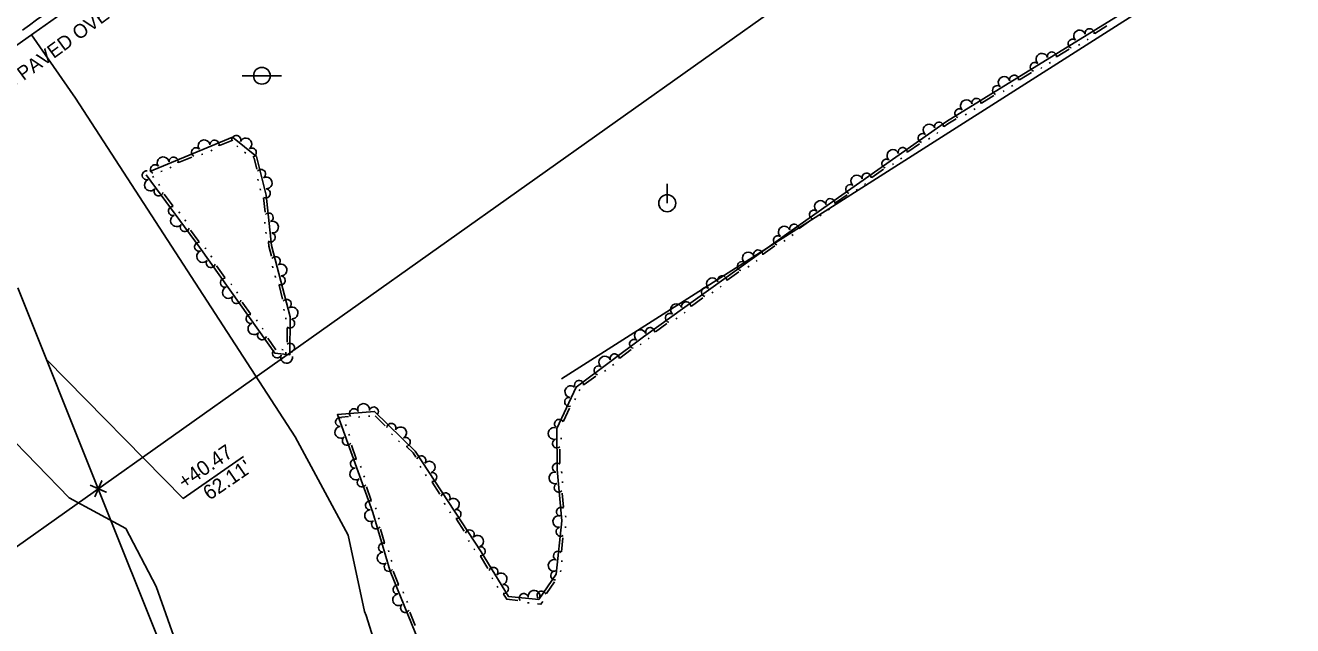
# Model space of a CAD drawing. Extents: x 1577032 to 1581865, y 611492 to 615011.
# Drawn here: x 1579793.8 to 1580157.3, y 613153.4 to 613325.8 of the extents above; entities that cross this region are included whole.
import ezdxf

# ---------------------------------------------------------------- set-up
doc = ezdxf.new("R2010")
doc.units = 0
for name, color, linetype in [('Exist Hydro Jurisdictional Stream or Body of Water', 7, 'Continuous'), ('Exist Other Culture Fence Line', 7, 'Continuous'), ('Exist Property Corner CELL', 7, 'Continuous'), ('Exist Property Line', 7, 'Continuous'), ('Exist Property Tie Line', 7, 'Continuous'), ('Exist Property Tie Line Leader', 7, 'Continuous'), ('Exist Property Tie Line Text', 7, 'Continuous'), ('Exist Right of Way Line', 7, 'Continuous'), ('Exist Roads EOT', 7, 'Continuous'), ('Exist Structure Major Deck Tunnel Box Culvert', 7, 'Continuous'), ('Exist Utilities Power Pole CELL', 7, 'Continuous'), ('Exist Utilities Telephone Pole CELL', 7, 'Continuous'), ('Old_Level_11', 7, 'Continuous'), ('Scratch_Level_3', 7, 'Continuous')]:
    doc.layers.add(name, color=color, linetype=linetype)

msp = doc.modelspace()

# ---------------------------------------------------------------- linework, layer by layer
at = {"layer": 'Exist Hydro Jurisdictional Stream or Body of Water'}
for points in [[(1579795.54, 613323.09), (1579808.15, 613304.86)], [(1579891.06, 613157.43), (1579886.36, 613179.34), (1579871.2, 613207.59), (1579808.15, 613304.86)], [(1579831.32, 613164.67), (1579822.56, 613181.34), (1579806.35, 613190.1), (1579787.81, 613209.26), (1579780.85, 613233.72), (1579753.99, 613271.61), (1579747.82, 613283.64), (1579744.18, 613286.7)], [(1579849.47, 613068.48), (1579851.27, 613081.33), (1579854.07, 613093.1), (1579856.83, 613105.74), (1579850.56, 613123.2), (1579837.45, 613147.36), (1579831.32, 613164.67)], [(1579881.95, 612966.49), (1579883.81, 612978.96), (1579885.26, 612993.89), (1579884.04, 613006.43), (1579886.63, 613016.25), (1579894.51, 613030.46), (1579900.22, 613050.87), (1579903.43, 613069.8), (1579906.17, 613093.25), (1579900.39, 613127.87), (1579891.53, 613156.32), (1579891.06, 613157.43)]]:
    msp.add_lwpolyline(points, dxfattribs=at)
at = {"layer": 'Exist Other Culture Fence Line'}
msp.add_line((1579947.54, 613224.25), (1580319.1, 613460.95), dxfattribs=at)
at = {"layer": 'Exist Property Corner CELL'}
msp.add_line((1579814.68, 613192.73), (1579814.68, 613192.73), dxfattribs=at)
msp.add_lwpolyline([(1579812.38, 613193.72), (1579816.97, 613191.75), (1579814.68, 613192.73), (1579815.66, 613195.03), (1579813.69, 613190.43)], dxfattribs=at)
at = {"layer": 'Exist Property Line'}
msp.add_line((1579859.46, 613080.55), (1579814.68, 613192.73), dxfattribs=at)
at = {"layer": 'Exist Property Tie Line'}
msp.add_line((1579791.65, 613250.42), (1579814.68, 613192.73), dxfattribs=at)
at = {"layer": 'Exist Property Tie Line Leader'}
msp.add_lwpolyline([(1579799.92, 613229.7), (1579839.05, 613189.94), (1579856.37, 613202.02)], dxfattribs=at)
at = {"layer": 'Exist Right of Way Line'}
msp.add_line((1578304.92, 612120.6), (1580458.22, 613649.74), dxfattribs=at)
at = {"layer": 'Exist Roads EOT'}
msp.add_lwpolyline([(1579792.91, 613324.43), (1579794.95, 613325.88), (1579796.98, 613327.33), (1579799.02, 613328.78), (1579801.06, 613330.23), (1579803.09, 613331.68), (1579805.13, 613333.13), (1579807.17, 613334.58), (1579809.21, 613336.02), (1579811.26, 613337.46), (1579813.3, 613338.89), (1579815.35, 613340.33), (1579817.39, 613341.77), (1579819.44, 613343.21), (1579821.48, 613344.64), (1579823.53, 613346.08), (1579825.57, 613347.52), (1579826.09, 613347.88)], dxfattribs=at)
at = {"layer": 'Exist Structure Major Deck Tunnel Box Culvert'}
msp.add_lwpolyline([(1579827.3, 613348.19), (1579814.88, 613365.36), (1579813.5, 613367.27), (1579799.63, 613357.47), (1579792.53, 613352.42), (1579770.02, 613336.52), (1579752.16, 613323.84), (1579739.02, 613314.56), (1579723.58, 613303.6), (1579719.7, 613300.83), (1579716.41, 613298.3), (1579718.14, 613295.84), (1579729.17, 613280.12), (1579731.04, 613277.46), (1579735.17, 613280.34), (1579753.85, 613293.54), (1579777.85, 613310.57), (1579796.19, 613323.54), (1579810.87, 613333.95), (1579825.71, 613344.51), (1579828.51, 613346.49)], close=True, dxfattribs=at)
at = {"layer": 'Exist Utilities Power Pole CELL'}
for q in [(1579977.88, 613280.32), (1579977.88, 613274.7)]:
    msp.add_line((1579977.88, 613274.7), q, dxfattribs=at)
msp.add_circle((1579977.88, 613274.7), 2.45, dxfattribs=at)
at = {"layer": 'Exist Utilities Telephone Pole CELL'}
for p, q in [((1579855.95, 613311.31), (1579867.28, 613311.31)), ((1579861.62, 613311.31), (1579861.62, 613311.31))]:
    msp.add_line(p, q, dxfattribs=at)
msp.add_circle((1579861.62, 613311.31), 2.41, dxfattribs=at)
at = {"layer": 'Old_Level_11'}
for points in [[(1579898.24, 612986.26), (1579907.01, 613012.55), (1579914.07, 613035.38), (1579922.37, 613060.98), (1579924.18, 613085.02), (1579920.71, 613110.77), (1579911.67, 613136.42), (1579898.39, 613169.04), (1579893.39, 613185.86), (1579883.29, 613213.99), (1579893.92, 613214.92), (1579905.6, 613203.51), (1579924.51, 613174.57), (1579932.36, 613161.75), (1579941.05, 613160.87), (1579945.99, 613168.16), (1579947.64, 613183.49), (1579946.28, 613198.23), (1579946.25, 613210.04), (1579951.72, 613221.88), (1579971.1, 613236.34), (1580013.43, 613266.8), (1580057.96, 613298.21), (1580109, 613329.66)], [(1580100.52, 613323.47), (1580104.01, 613325.63)], [(1580098.29, 613321.62), (1580098.64, 613321.84)], [(1580089.7, 613316.8), (1580093.19, 613318.96)], [(1580095.85, 613320.11), (1580096.2, 613320.33)], [(1580085.03, 613313.44), (1580085.38, 613313.66)], [(1580087.47, 613314.95), (1580087.82, 613315.16)], [(1580078.88, 613310.13), (1580082.37, 613312.29)], [(1580074.2, 613306.77), (1580074.55, 613306.99)], [(1580076.65, 613308.28), (1580077, 613308.49)], [(1580068.05, 613303.46), (1580071.54, 613305.62)], [(1580057.32, 613296.75), (1580058.41, 613297.53), (1580060.72, 613298.95)], [(1580063.38, 613300.1), (1580063.73, 613300.32)], [(1580065.82, 613301.61), (1580066.17, 613301.82)], [(1579829.46, 613283.82), (1579853.23, 613293.7), (1579860.11, 613288.12), (1579862.87, 613276.99), (1579864.41, 613262.57), (1579869.72, 613242.08), (1579869.67, 613231.18), (1579865.28, 613231.66), (1579855.5, 613245.54), (1579843.72, 613262.07), (1579828.46, 613282.9)], [(1579849.47, 613291.25), (1579853.25, 613292.83)], [(1580046.93, 613289.42), (1580050.28, 613291.79)], [(1580052.87, 613293.11), (1580053.2, 613293.35)], [(1580055.21, 613294.76), (1580055.54, 613295)], [(1579837.73, 613286.37), (1579841.51, 613287.95)], [(1579844.32, 613288.67), (1579844.7, 613288.83)], [(1579846.97, 613289.77), (1579847.35, 613289.93)], [(1579854.44, 613291.14), (1579854.76, 613290.88)], [(1579856.67, 613289.33), (1579856.99, 613289.07)], [(1579859.16, 613287.84), (1579859.38, 613287.66), (1579860.16, 613284.49)], [(1579835.24, 613284.89), (1579835.61, 613285.05)], [(1580036.54, 613282.1), (1580039.89, 613284.46)], [(1580042.47, 613285.78), (1580042.81, 613286.02)], [(1580044.82, 613287.43), (1580045.15, 613287.67)], [(1579830.55, 613282.13), (1579830.31, 613282.46)], [(1579832.58, 613283.79), (1579832.96, 613283.95)], [(1579860.46, 613281.61), (1579860.56, 613281.21)], [(1579832.25, 613279.82), (1579832.01, 613280.15)], [(1579836.04, 613273.95), (1579833.61, 613277.26)], [(1579861.15, 613278.82), (1579861.24, 613278.42)], [(1580026.15, 613274.77), (1580029.5, 613277.13)], [(1580032.09, 613278.45), (1580032.42, 613278.69)], [(1580034.43, 613280.11), (1580034.77, 613280.35)], [(1579862.12, 613276.23), (1579862.56, 613272.15)], [(1579838.06, 613271.88), (1579837.82, 613272.21)], [(1579839.76, 613269.56), (1579839.52, 613269.89)], [(1580015.76, 613267.44), (1580019.11, 613269.81)], [(1580021.7, 613271.13), (1580022.03, 613271.36)], [(1580024.04, 613272.78), (1580024.38, 613273.02)], [(1579843.55, 613263.69), (1579841.12, 613267)], [(1579862.46, 613269.25), (1579862.5, 613268.84)], [(1579862.76, 613266.4), (1579862.81, 613265.99)], [(1579863.48, 613263.59), (1579863.6, 613262.42), (1579864.37, 613259.47)], [(1580005.44, 613260.04), (1580008.77, 613262.43)], [(1580011.33, 613263.78), (1580011.67, 613264.02)], [(1580013.66, 613265.45), (1580014, 613265.69)], [(1579845.57, 613261.59), (1579845.33, 613261.93)], [(1579847.23, 613259.25), (1579847, 613259.59)], [(1579850.95, 613253.34), (1579848.57, 613256.68)], [(1579864.69, 613256.59), (1579864.79, 613256.19)], [(1580001.02, 613256.35), (1580001.35, 613256.59)], [(1580003.35, 613258.03), (1580003.68, 613258.27)], [(1579852.95, 613251.24), (1579852.71, 613251.57)], [(1579865.41, 613253.81), (1579865.51, 613253.41)], [(1579995.12, 613252.61), (1579998.45, 613255.01)], [(1579854.62, 613248.9), (1579854.38, 613249.24)], [(1579866.53, 613251.13), (1579867.55, 613247.16)], [(1579990.7, 613248.93), (1579991.03, 613249.17)], [(1579993.03, 613250.6), (1579993.36, 613250.84)], [(1579858.31, 613242.97), (1579856.17, 613246.02), (1579855.95, 613246.33)], [(1579867.88, 613244.28), (1579867.98, 613243.88)], [(1579984.8, 613245.19), (1579988.13, 613247.58)], [(1579860.3, 613240.86), (1579860.07, 613241.2)], [(1579868.49, 613241.8), (1579868.49, 613241.39)], [(1579980.38, 613241.5), (1579980.71, 613241.74)], [(1579982.71, 613243.18), (1579983.04, 613243.42)], [(1579861.95, 613238.52), (1579861.72, 613238.85)], [(1579868.88, 613238.93), (1579868.87, 613234.83)], [(1579974.48, 613237.76), (1579977.81, 613240.16)], [(1579865.63, 613232.58), (1579863.27, 613235.93)], [(1579970.1, 613234.06), (1579970.43, 613234.3)], [(1579972.39, 613235.75), (1579972.72, 613235.99)], [(1579867.72, 613232.63), (1579867.31, 613232.67)], [(1579868.44, 613231.96), (1579868.44, 613231.55)], [(1579964.27, 613230.22), (1579967.55, 613232.67)], [(1579959.91, 613226.45), (1579960.24, 613226.7)], [(1579962.21, 613228.17), (1579962.54, 613228.42)], [(1579954.08, 613222.61), (1579957.36, 613225.07)], [(1579952.61, 613220.87), (1579952.78, 613221.24)], [(1579948.11, 613212.11), (1579949.83, 613215.83)], [(1579951.41, 613218.26), (1579951.58, 613218.63)], [(1579884.42, 613213.26), (1579886.44, 613213.44)], [(1579889.33, 613213.28), (1579889.74, 613213.32)], [(1579892.19, 613213.53), (1579892.6, 613213.57)], [(1579894.08, 613213.62), (1579897.02, 613210.75)], [(1579885.76, 613210.75), (1579885.62, 613211.13)], [(1579886.73, 613208.05), (1579886.59, 613208.43)], [(1579898.78, 613208.45), (1579899.08, 613208.16)], [(1579947.48, 613209.77), (1579947.45, 613209.7)], [(1579888.7, 613201.35), (1579887.31, 613205.21)], [(1579900.84, 613206.44), (1579901.13, 613206.16)], [(1579903.18, 613204.73), (1579904.96, 613202.99), (1579905.74, 613201.79)], [(1579947.49, 613206.96), (1579947.48, 613207.37)], [(1579947.1, 613199.99), (1579947.09, 613204.09)], [(1579890.06, 613198.78), (1579889.92, 613199.17)], [(1579906.97, 613199.17), (1579907.19, 613198.82)], [(1579947.61, 613197.23), (1579947.57, 613197.64)], [(1579891.03, 613196.08), (1579890.89, 613196.47)], [(1579908.54, 613196.76), (1579908.76, 613196.42)], [(1579910.45, 613194.58), (1579912.7, 613191.15)], [(1579947.87, 613194.37), (1579947.84, 613194.78)], [(1579893, 613189.38), (1579891.61, 613193.24)], [(1579948.1, 613187.39), (1579947.73, 613191.47)], [(1579894.35, 613186.82), (1579894.21, 613187.2)], [(1579913.92, 613188.53), (1579914.15, 613188.18)], [(1579915.49, 613186.12), (1579915.72, 613185.78)], [(1579895.22, 613184.01), (1579895.1, 613184.4)], [(1579917.41, 613183.94), (1579919.65, 613180.51)], [(1579948.77, 613184.57), (1579948.74, 613184.98)], [(1579896.81, 613177.21), (1579895.65, 613181.14)], [(1579948.66, 613181.47), (1579948.7, 613181.88)], [(1579920.88, 613177.88), (1579921.1, 613177.54)], [(1579922.45, 613175.48), (1579922.67, 613175.14)], [(1579947.51, 613174.58), (1579947.94, 613178.66)], [(1579898.03, 613174.57), (1579897.91, 613174.97)], [(1579898.84, 613171.82), (1579898.73, 613172.22)], [(1579924.33, 613173.31), (1579926.47, 613169.81)], [(1579947.61, 613171.68), (1579947.65, 613172.09)], [(1579900.82, 613165.24), (1579899.27, 613169.04)], [(1579947.3, 613168.83), (1579947.35, 613169.23)], [(1579927.61, 613167.15), (1579927.83, 613166.8)], [(1579929.11, 613164.7), (1579929.33, 613164.35)], [(1579943.21, 613162.59), (1579945.51, 613165.99)], [(1579902.28, 613162.74), (1579902.13, 613163.12)], [(1579930.96, 613162.46), (1579931.87, 613160.98), (1579935.03, 613160.66)], [(1579903.36, 613160.08), (1579903.21, 613160.46)], [(1579905.61, 613153.47), (1579904.07, 613157.27)], [(1579937.84, 613159.96), (1579938.25, 613159.92)], [(1579940.7, 613159.67), (1579941.66, 613159.57), (1579942.17, 613160.33)]]:
    msp.add_lwpolyline(points, dxfattribs=at)
for centre, radius, start, end in [((1580096.17, 613322.72), 1.69, 17.6074, 225.6799), ((1580099.04, 613323.53), 1.3, 352.4121, 193.2087), ((1580094.16, 613320.51), 1.3, 50.0786, 250.8752), ((1580085.35, 613316.05), 1.69, 17.6074, 225.6799), ((1580088.22, 613316.86), 1.3, 352.4121, 193.2087), ((1580083.33, 613313.85), 1.3, 50.0786, 250.8752), ((1580074.52, 613309.38), 1.69, 17.6074, 225.6799), ((1580077.4, 613310.19), 1.3, 352.4121, 193.2087), ((1580072.51, 613307.18), 1.3, 50.0786, 250.8752), ((1580063.7, 613302.71), 1.69, 17.6074, 225.6799), ((1580066.57, 613303.52), 1.3, 352.4121, 193.2087), ((1580061.69, 613300.51), 1.3, 50.0786, 250.8752), ((1580053.02, 613295.73), 1.69, 21.1591, 229.2316), ((1580055.84, 613296.71), 1.3, 355.9638, 196.7604), ((1579845.05, 613291.19), 1.69, 8.5377, 216.6102), ((1579848.02, 613291.54), 1.3, 343.3424, 184.139), ((1579854.26, 613292.87), 1.3, 339.3717, 180.1683), ((1579857.01, 613291.7), 1.69, 306.9005, 154.973), ((1580051.15, 613293.4), 1.3, 53.6303, 254.4269), ((1579833.31, 613286.31), 1.69, 8.5377, 216.6102), ((1579836.28, 613286.66), 1.3, 343.3424, 184.139), ((1579842.71, 613289.33), 1.3, 41.0089, 241.8055), ((1579858.72, 613289.25), 1.3, 281.7052, 122.5018), ((1580042.63, 613288.4), 1.69, 21.1591, 229.2316), ((1580045.45, 613289.39), 1.3, 355.9638, 196.7604), ((1579830.98, 613284.45), 1.3, 41.0089, 241.8055), ((1579861.36, 613283.1), 1.3, 302.3301, 143.1266), ((1580040.76, 613286.08), 1.3, 53.6303, 254.4269), ((1579828.59, 613282.73), 1.3, 86.9821, 287.7787), ((1579829.62, 613279.93), 1.69, 112.1774, 320.2499), ((1579862.84, 613280.51), 1.69, 269.8589, 117.9314), ((1580032.24, 613281.07), 1.69, 21.1591, 229.2316), ((1580035.06, 613282.06), 1.3, 355.9638, 196.7604), ((1579831.98, 613278.1), 1.3, 144.6486, 345.4451), ((1579862.73, 613277.52), 1.3, 244.6636, 85.4602), ((1580030.37, 613278.75), 1.3, 53.6303, 254.4269), ((1579836.1, 613272.47), 1.3, 86.9821, 287.7787), ((1580021.85, 613273.75), 1.69, 21.1591, 229.2316), ((1580024.67, 613274.73), 1.3, 355.9638, 196.7604), ((1579837.13, 613269.67), 1.69, 112.1774, 320.2499), ((1579863.55, 613270.6), 1.3, 294.5479, 135.3445), ((1580019.98, 613271.42), 1.3, 53.6303, 254.4269), ((1579839.49, 613267.84), 1.3, 144.6486, 345.4451), ((1579864.16, 613264.9), 1.3, 236.8815, 77.678), ((1579864.67, 613267.84), 1.69, 262.0767, 110.1492), ((1580011.47, 613266.4), 1.69, 21.7027, 229.7752), ((1580014.28, 613267.4), 1.3, 355.9638, 196.7604), ((1579843.61, 613262.21), 1.3, 86.9821, 287.7787), ((1580009.62, 613264.06), 1.3, 54.1739, 254.9705), ((1579844.61, 613259.4), 1.69, 111.4524, 319.5249), ((1579865.57, 613258.09), 1.3, 302.9591, 143.7556), ((1580001.15, 613258.97), 1.69, 21.7027, 229.7752), ((1580003.96, 613259.99), 1.3, 356.5074, 197.304), ((1579846.95, 613257.54), 1.3, 143.9236, 344.7202), ((1579867.09, 613255.51), 1.69, 270.4879, 118.5604), ((1579999.3, 613256.63), 1.3, 54.1739, 254.9705), ((1579850.99, 613251.86), 1.3, 86.2572, 287.0537), ((1579867.01, 613252.53), 1.3, 245.2926, 86.0892), ((1579990.83, 613251.55), 1.69, 21.7027, 229.7752), ((1579993.64, 613252.56), 1.3, 356.5074, 197.304), ((1579851.99, 613249.05), 1.69, 111.4524, 319.5249), ((1579854.33, 613247.19), 1.3, 143.9236, 344.7202), ((1579988.98, 613249.21), 1.3, 54.1739, 254.9705), ((1579868.76, 613245.78), 1.3, 302.9591, 143.7556), ((1579870.27, 613243.2), 1.69, 270.4879, 118.5604), ((1579980.51, 613244.12), 1.69, 21.7027, 229.7752), ((1579983.32, 613245.13), 1.3, 356.5074, 197.304), ((1579858.35, 613241.5), 1.3, 85.9269, 286.7235), ((1579869.71, 613240.16), 1.3, 230.5054, 71.302), ((1579978.66, 613241.78), 1.3, 54.1739, 254.9705), ((1579859.33, 613238.68), 1.69, 111.1222, 319.1947), ((1579861.66, 613236.8), 1.3, 143.5934, 344.3899), ((1579970.19, 613236.68), 1.69, 22.7003, 230.7728), ((1579973, 613237.71), 1.3, 356.5074, 197.304), ((1579869.68, 613233.19), 1.3, 288.1719, 128.9685), ((1579968.38, 613234.31), 1.3, 55.1715, 255.9681), ((1579865.96, 613231.59), 1.3, 134.5211, 335.3177), ((1579868.72, 613230.46), 1.69, 159.7164, 7.7889), ((1579960, 613229.08), 1.69, 22.7003, 230.7728), ((1579962.79, 613230.14), 1.3, 357.5051, 198.3016), ((1579958.19, 613226.7), 1.3, 55.1715, 255.9681), ((1579952.6, 613222.53), 1.3, 357.5051, 198.3016), ((1579949.77, 613217.66), 1.3, 83.6163, 284.4129), ((1579950.23, 613220.61), 1.69, 51.1451, 259.2176), ((1579888, 613214.4), 1.3, 23.4516, 224.2482), ((1579890.79, 613215.47), 1.69, 350.9804, 199.0529), ((1579893.72, 613214.9), 1.3, 325.7851, 166.5817), ((1579884.05, 613211.88), 1.3, 70.5195, 271.3161), ((1579946.85, 613211.33), 1.3, 25.9498, 226.7464), ((1579884.24, 613208.9), 1.69, 95.7148, 303.7873), ((1579898.76, 613210.19), 1.3, 334.0985, 174.8951), ((1579901.39, 613208.77), 1.69, 301.6273, 149.6998), ((1579945.43, 613208.59), 1.69, 76.1428, 284.2153), ((1579885.99, 613206.47), 1.3, 128.186, 328.9826), ((1579902.87, 613206.18), 1.3, 276.432, 117.2286), ((1579946.26, 613205.72), 1.3, 108.614, 309.4106), ((1579888.34, 613199.91), 1.3, 70.5195, 271.3161), ((1579907.33, 613200.87), 1.3, 321.6014, 162.398), ((1579909.58, 613198.92), 1.69, 289.1302, 137.2027), ((1579888.54, 613196.93), 1.69, 95.7148, 303.7873), ((1579910.47, 613196.06), 1.3, 263.9349, 104.7315), ((1579945.68, 613195.82), 1.69, 81.2177, 289.2902), ((1579946.28, 613198.75), 1.3, 50.9476, 251.7441), ((1579890.28, 613194.51), 1.3, 128.186, 328.9826), ((1579946.76, 613193.03), 1.3, 113.6889, 314.4855), ((1579914.28, 613190.23), 1.3, 321.6014, 162.398), ((1579916.54, 613188.27), 1.69, 289.1302, 137.2027), ((1579892.79, 613185), 1.69, 92.5176, 300.5901), ((1579892.64, 613187.95), 1.3, 70.5195, 271.3161), ((1579917.42, 613185.42), 1.3, 263.9349, 104.7315), ((1579947.4, 613186.09), 1.3, 56.0224, 256.819), ((1579894.39, 613182.48), 1.3, 124.9888, 325.7853), ((1579946.79, 613183.32), 1.69, 69.8376, 277.9101), ((1579921.24, 613179.59), 1.3, 321.6014, 162.398), ((1579923.49, 613177.63), 1.69, 289.1302, 137.2027), ((1579947.3, 613180.38), 1.3, 102.3088, 303.1054), ((1579896.38, 613175.8), 1.3, 67.3223, 268.1189), ((1579924.38, 613174.78), 1.3, 263.9349, 104.7315), ((1579896.41, 613172.81), 1.69, 92.5176, 300.5901), ((1579945.44, 613170.68), 1.69, 69.8376, 277.9101), ((1579946.56, 613173.45), 1.3, 44.6424, 245.4389), ((1579898.01, 613170.29), 1.3, 124.9888, 325.7853), ((1579928.02, 613168.84), 1.3, 319.905, 160.7016), ((1579930.22, 613166.82), 1.69, 287.4338, 135.5063), ((1579945.75, 613167.81), 1.3, 74.3202, 275.1168), ((1579900.52, 613163.79), 1.3, 72.9212, 273.7178), ((1579931.02, 613163.94), 1.3, 262.2385, 103.0351), ((1579900.85, 613160.83), 1.69, 98.1165, 306.189), ((1579936.74, 613161.31), 1.3, 12.6436, 213.4401), ((1579939.68, 613161.83), 1.69, 340.1724, 188.2448), ((1579941.84, 613162.04), 1.3, 16.6537, 217.4503), ((1579902.69, 613158.48), 1.3, 130.5877, 331.3843)]:
    msp.add_arc(centre, radius, start, end, dxfattribs=at)

# ---------------------------------------------------------------- texts
at = {"layer": 'Exist Property Tie Line Text'}
for s, p in [('+40.47', (1579839.4, 613192.45)), ("62.11'", (1579846.57, 613189.25))]:
    msp.add_text(s, height=4.2, rotation=34.4104, dxfattribs=at).set_placement(p)
at = {"layer": 'Scratch_Level_3'}
msp.add_text('BRIDGE SEAMS PAVED OVER', height=4, rotation=36.2551, dxfattribs=at).set_placement((1579759.22, 613284.8))

doc.saveas('drawing.dxf')
